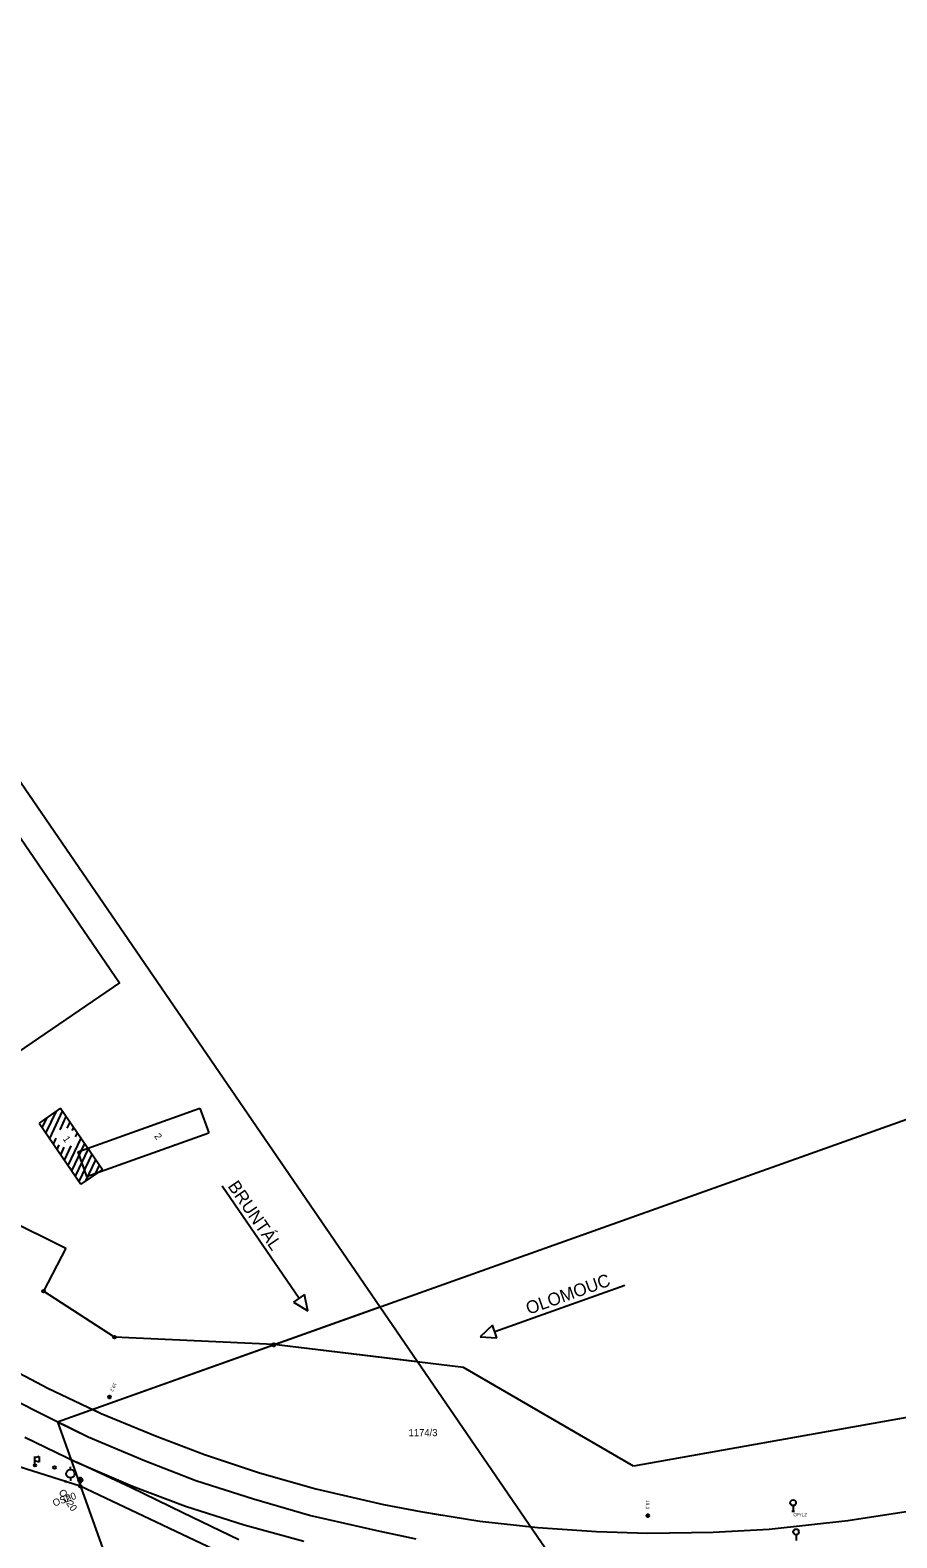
# Model space of a CAD drawing. Extents: x -734423 to 647242, y -1165906 to -111601.
# Drawn here: x -533105.5 to -532951.8, y -1114430.9 to -1114163.4 of the extents above; entities that cross this region are included whole.
import ezdxf

# ---------------------------------------------------------------- set-up
doc = ezdxf.new("R2010")
doc.units = 0
for name, color, linetype in [('Vrstva 1', 7, 'Continuous'), ('Vrstva 11', 7, 'Continuous'), ('Vrstva 14', 7, 'Continuous'), ('Vrstva 15', 7, 'Continuous'), ('Vrstva 16', 7, 'Continuous'), ('Vrstva 2', 7, 'Continuous'), ('Vrstva 26', 7, 'Continuous'), ('Vrstva 3', 7, 'Continuous'), ('Vrstva 4', 7, 'Continuous'), ('Vrstva 8', 7, 'Continuous')]:
    doc.layers.add(name, color=color, linetype=linetype)

msp = doc.modelspace()

# ---------------------------------------------------------------- linework, layer by layer
at = {"layer": 'Vrstva 1'}
for p, q in [((-533071.41, -1114368.44), (-533057.78, -1114388.35)), ((-533000.02, -1114386.07), (-533023.09, -1114394.3)), ((-533056.82, -1114387.7), (-533058.78, -1114389.04)), ((-533056.23, -1114390.61), (-533056.82, -1114387.7)), ((-533058.78, -1114389.04), (-533056.23, -1114390.61)), ((-533023.51, -1114393.15), (-533025.67, -1114395.22)), ((-533022.71, -1114395.39), (-533023.51, -1114393.15)), ((-533025.67, -1114395.22), (-533022.71, -1114395.39))]:
    msp.add_line(p, q, dxfattribs=at)
at = {"layer": 'Vrstva 14'}
for p, q in [((-533109.81, -1114374.13), (-533099.15, -1114379.47)), ((-533099.15, -1114379.47), (-533103.12, -1114387.1)), ((-533090.49, -1114395.26), (-533103.12, -1114387.1)), ((-533062.24, -1114396.58), (-533090.49, -1114395.26)), ((-533062.24, -1114396.58), (-533062.28, -1114396.58)), ((-533028.61, -1114400.63), (-533062.24, -1114396.58)), ((-533036.73, -1114399.65), (-533062.24, -1114396.58)), ((-532875.63, -1114396.29), (-532998.5, -1114418.11)), ((-532998.5, -1114418.11), (-533028.61, -1114400.63))]:
    msp.add_line(p, q, dxfattribs=at)
at = {"layer": 'Vrstva 15'}
for p, q in [((-533112.03, -1114399.2), (-533102.35, -1114404.3)), ((-533104.45, -1114408.4), (-533114.42, -1114403.28)), ((-533102.35, -1114404.3), (-533092.87, -1114408.78)), ((-533095.15, -1114413), (-533104.45, -1114408.4)), ((-533094.43, -1114408.04), (-533092.87, -1114408.78)), ((-533092.87, -1114408.78), (-533083.26, -1114412.78)), ((-533095.15, -1114413), (-533100.6, -1114410.31)), ((-533083.26, -1114412.78), (-533074.56, -1114416.07)), ((-533106.41, -1114412.97), (-533097.24, -1114417.42)), ((-533085.21, -1114417.2), (-533095.15, -1114413)), ((-533104.61, -1114417.78), (-533104.61, -1114416.43)), ((-533103.86, -1114416.43), (-533104.61, -1114416.68)), ((-533103.86, -1114417.43), (-533104.61, -1114417.18)), ((-533103.86, -1114416.43), (-533103.86, -1114417.43)), ((-533098.23, -1114416.94), (-533097.24, -1114417.42)), ((-533097.24, -1114417.42), (-533087.33, -1114421.7)), ((-533087.6, -1114421.92), (-533097.24, -1114417.42)), ((-533076.11, -1114420.72), (-533085.21, -1114417.2)), ((-533074.56, -1114416.07), (-533064.77, -1114419.32)), ((-533098.33, -1114418.73), (-533098.33, -1114418.23)), ((-533098.33, -1114420.23), (-533098.33, -1114420.73)), ((-533096.83, -1114420.84), (-533096.31, -1114420.31)), ((-533096.83, -1114420.31), (-533096.31, -1114420.84)), ((-533096.83, -1114420.84), (-533096.31, -1114420.31)), ((-533096.83, -1114420.31), (-533096.31, -1114420.84)), ((-533065.86, -1114423.98), (-533076.11, -1114420.72)), ((-533064.77, -1114419.32), (-533054.78, -1114422.16)), ((-533096.57, -1114420.95), (-533096.57, -1114421.5)), ((-533096.57, -1114420.95), (-533096.57, -1114421.5)), ((-533078.37, -1114426.41), (-533087.6, -1114421.92)), ((-533087.33, -1114421.7), (-533077.91, -1114425.25)), ((-533054.78, -1114422.16), (-533042.8, -1114424.92)), ((-533077.91, -1114425.25), (-533067.5, -1114428.57)), ((-533055.91, -1114426.89), (-533065.86, -1114423.98)), ((-533042.8, -1114424.92), (-533036.22, -1114426.2)), ((-533036.22, -1114426.2), (-533025.75, -1114427.87)), ((-533036.22, -1114426.2), (-533032.38, -1114426.81)), ((-532970.43, -1114426.13), (-532969.93, -1114426.13)), ((-532970.18, -1114425.13), (-532970.18, -1114426.13)), ((-532960.48, -1114427.8), (-532950.12, -1114426.21)), ((-533068.48, -1114431.18), (-533078.37, -1114426.41)), ((-533067.5, -1114428.57), (-533056.96, -1114431.45)), ((-533043.39, -1114429.75), (-533055.91, -1114426.89)), ((-533025.75, -1114427.87), (-533015.45, -1114429.02)), ((-532974.45, -1114429.32), (-532960.48, -1114427.8)), ((-533037, -1114431.06), (-533043.39, -1114429.75)), ((-533038.37, -1114430.78), (-533043.39, -1114429.75)), ((-533015.45, -1114429.02), (-533005.02, -1114429.74)), ((-533005.02, -1114429.74), (-532995.94, -1114430.01)), ((-532995.94, -1114430.01), (-532984.34, -1114429.87)), ((-532984.34, -1114429.87), (-532974.45, -1114429.32)), ((-532969.66, -1114430.3), (-532969.66, -1114431.3))]:
    msp.add_line(p, q, dxfattribs=at)
msp.add_lwpolyline([(-533096.6, -1114421.5), (-533096.47, -1114421.87)], dxfattribs=at)
for centre, radius in [((-533104.61, -1114417.98), 0.2), ((-533101.14, -1114418.39), 0.25), ((-533098.33, -1114419.48), 0.75), ((-533096.57, -1114420.57), 0.375), ((-533096.57, -1114421.7), 0.2), ((-532970.18, -1114424.63), 0.5), ((-532969.66, -1114429.8), 0.5)]:
    msp.add_circle(centre, radius, dxfattribs=at)
for centre, radius, start, end in [((-533096.57, -1114420.57), 0.375, 223.2592, 175.989), ((-533096.57, -1114421.7), 0.2, 299.4948, 99.7534)]:
    msp.add_arc(centre, radius, start, end, dxfattribs=at)
at = {"layer": 'Vrstva 16'}
for p, q in [((-533103.12, -1114387.1), (-533103.12, -1114387.1)), ((-533090.49, -1114395.26), (-533090.49, -1114395.26)), ((-533062.24, -1114396.58), (-533062.24, -1114396.58)), ((-533062.24, -1114396.58), (-533062.24, -1114396.58))]:
    msp.add_line(p, q, dxfattribs=at)
msp.add_lwpolyline([(-533062.2, -1114396.55), (-533062.29, -1114396.58)], dxfattribs=at)
for centre, radius in [((-533103.12, -1114387.1), 0.258), ((-533103.12, -1114387.1), 0.25), ((-533103.12, -1114387.1), 0.05), ((-533103.12, -1114387.1), 0.05), ((-533090.49, -1114395.26), 0.258), ((-533090.49, -1114395.26), 0.25), ((-533090.49, -1114395.26), 0.05), ((-533090.49, -1114395.26), 0.05), ((-533062.24, -1114396.58), 0.258), ((-533062.24, -1114396.58), 0.25), ((-533062.24, -1114396.58), 0.05), ((-533062.24, -1114396.58), 0.05)]:
    msp.add_circle(centre, radius, dxfattribs=at)
for radius, start, end in [(0.258, 196.3173, 22.9305), (0.25, 196.2073, 23.0405), (0.05, 182.2875, 36.9602), (0.05, 182.2875, 36.9602)]:
    msp.add_arc((-533062.24, -1114396.58), radius, start, end, dxfattribs=at)
at = {"layer": 'Vrstva 2'}
for p, q in [((-533103.31, -1114358.13), (-533102.44, -1114356.29)), ((-533102.66, -1114359.08), (-533100.8, -1114355.17)), ((-533102, -1114360.04), (-533099.7, -1114355.18)), ((-533100.16, -1114358.48), (-533099.05, -1114356.14)), ((-533098.9, -1114358.16), (-533098.39, -1114357.09)), ((-533097.99, -1114358.58), (-533097.74, -1114358.05)), ((-533097.42, -1114359.7), (-533097.08, -1114359)), ((-533101.35, -1114360.99), (-533100.85, -1114359.95)), ((-533100.69, -1114361.95), (-533100.31, -1114361.13)), ((-533100.04, -1114362.9), (-533099.41, -1114361.56)), ((-533099.39, -1114363.85), (-533098.17, -1114361.29)), ((-533098.73, -1114364.81), (-533096.43, -1114359.96)), ((-533098.08, -1114365.76), (-533095.78, -1114360.91)), ((-533097.42, -1114366.72), (-533095.12, -1114361.87)), ((-533096.77, -1114367.67), (-533094.47, -1114362.82)), ((-533095.58, -1114367.51), (-533093.82, -1114363.78)), ((-533093.95, -1114366.38), (-533093.16, -1114364.73))]:
    msp.add_line(p, q, dxfattribs=at)
for points in [[(-532938.68, -1114445.35), (-532955.05, -1114450.16), (-532982.46, -1114453.31), (-533019.39, -1114451.2), (-533033.81, -1114448.46), (-533048.26, -1114444.23), (-533066.17, -1114436.13), (-533096.57, -1114421.7), (-533108.74, -1114417.84), (-533132.23, -1114402.06), (-533122.71, -1114388.35), (-533146.58, -1114370.65), (-533164.36, -1114353.16), (-533168.69, -1114352.21), (-533182.96, -1114335.24), (-533202.15, -1114309.37), (-533216.94, -1114286.74), (-533234.45, -1114259.44), (-533245.89, -1114237.86), (-533248.09, -1114233.45), (-533249.36, -1114234.02)], [(-533053.34, -1114441.93), (-533066.17, -1114436.13), (-533096.57, -1114421.7), (-533108.74, -1114417.84), (-533132.23, -1114402.06), (-533122.71, -1114388.35), (-533146.58, -1114370.65), (-533164.36, -1114353.16), (-533168.27, -1114352.2), (-533182.96, -1114335.24), (-533202.15, -1114309.37), (-533216.94, -1114286.74), (-533234.45, -1114259.44), (-533245.89, -1114237.86), (-533247.92, -1114233.69), (-533248.95, -1114234.18)], [(-533062.29, -1114396.58), (-533062.48, -1114396.65)], [(-533062.01, -1114396.48), (-533062.2, -1114396.55)]]:
    msp.add_lwpolyline(points, dxfattribs=at)
at = {"layer": 'Vrstva 26'}
for centre, radius in [((-533091.41, -1114405.87), 0.25), ((-533091.41, -1114405.87), 0.05), ((-532995.96, -1114426.92), 0.25), ((-532995.96, -1114426.92), 0.05)]:
    msp.add_circle(centre, radius, dxfattribs=at)
at = {"layer": 'Vrstva 3'}
msp.add_lwpolyline([(-533131.97, -1114270.53), (-533089.61, -1114332.39), (-533109.95, -1114346.32), (-533152.31, -1114284.47)], close=True, dxfattribs=at)
at = {"layer": 'Vrstva 4'}
for p, q in [((-533198.3, -1114163.75), (-532960.97, -1114510.27)), ((-533100.62, -1114410.25), (-532408.31, -1114163.4)), ((-533100.06, -1114354.66), (-533103.89, -1114357.28)), ((-533100.06, -1114354.66), (-533092.64, -1114365.49)), ((-533097.01, -1114362.37), (-533075.37, -1114354.65)), ((-533075.37, -1114354.65), (-533073.81, -1114359.02)), ((-533103.89, -1114357.28), (-533096.47, -1114368.11)), ((-533095.45, -1114366.74), (-533073.81, -1114359.02)), ((-533101.91, -1114359.91), (-533102.03, -1114359.99)), ((-533080.04, -1114361.09), (-533079.99, -1114361.23)), ((-533076.95, -1114359.99), (-533076.9, -1114360.12)), ((-533100.06, -1114362.62), (-533100.18, -1114362.7)), ((-533097.01, -1114362.37), (-533095.45, -1114366.74)), ((-533089.31, -1114364.4), (-533089.27, -1114364.53)), ((-533086.22, -1114363.3), (-533086.17, -1114363.43)), ((-533083.13, -1114362.19), (-533083.08, -1114362.33)), ((-533098.21, -1114365.33), (-533098.32, -1114365.41)), ((-533092.64, -1114365.49), (-533096.47, -1114368.11)), ((-533092.4, -1114365.5), (-533092.36, -1114365.63)), ((-533100.62, -1114410.25), (-533043.44, -1114389.86)), ((-533100.62, -1114410.25), (-533050.74, -1114550.12)), ((-533100.62, -1114410.25), (-533082.21, -1114461.88))]:
    msp.add_line(p, q, dxfattribs=at)

# ---------------------------------------------------------------- texts
at = {"layer": 'Vrstva 1'}
for s, rotation, p in [('BRUNTÁL', 304.4063, (-533070.52, -1114368.47)), ('OLOMOUC', 19.6237, (-533017.07, -1114391.29))]:
    msp.add_text(s, height=2.257, rotation=rotation, dxfattribs=at).set_placement(p)
at = {"layer": 'Vrstva 11'}
msp.add_text('1174/3', height=1.25, rotation=359.9996, dxfattribs=at).set_placement((-533038.36, -1114412.82))
at = {"layer": 'Vrstva 26'}
for s, rotation, p in [('19,2', 244.6987, (-533090.64, -1114403.27)), ('19,3', 268.3068, (-532996.25, -1114424.16))]:
    msp.add_text(s, height=0.6, rotation=rotation, dxfattribs=at).set_placement(p)
for s, p in [('4', (-533099.41, -1114421.21)), ('OPrL2', (-532970.14, -1114427.04))]:
    msp.add_text(s, height=0.6, dxfattribs=at).set_placement(p)
at = {"layer": 'Vrstva 3'}
for s, p in [('2', (-533083.53, -1114359.61)), ('1', (-533099.74, -1114360.08))]:
    msp.add_text(s, height=1.25, rotation=304.3772, dxfattribs=at).set_placement(p)
at = {"layer": 'Vrstva 8'}
for rotation, p in [(19.5946, (-533101.2, -1114425.32)), (304.3772, (-533100.48, -1114422.76))]:
    msp.add_text('OS20', height=1.248, rotation=rotation, dxfattribs=at).set_placement(p)

doc.saveas('drawing.dxf')
